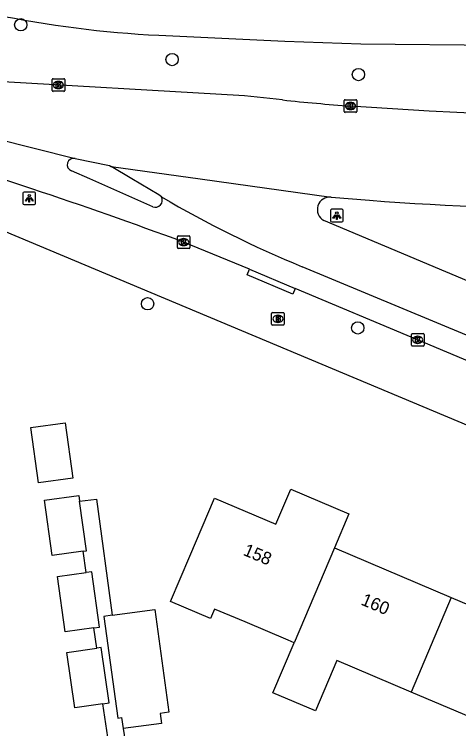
# Model space of a CAD drawing. Extents: x 162074 to 163034, y 381824 to 382557.
# Drawn here: x 162501.6 to 162536.8, y 382456.5 to 382513 of the extents above; entities that cross this region are included whole.
import ezdxf

# ---------------------------------------------------------------- set-up
doc = ezdxf.new("R2010")
doc.units = 0
for name, color, linetype in [('IMGEO_Boom', 7, 'Continuous'), ('IMGEO_Brandkraan', 7, 'Continuous'), ('IMGEO_Fietspad_gesloten', 7, 'Continuous'), ('IMGEO_Kolk', 7, 'Continuous'), ('IMGEO_Lichtpunt', 7, 'Continuous'), ('IMGEO_Pand', 7, 'Continuous'), ('IMGEO_Pand_nummerreeks', 7, 'Continuous'), ('IMGEO_Rijbaan_lokaal_gesloten', 7, 'Continuous'), ('IMGEO_Rijbaan_lokaal_open', 7, 'Continuous'), ('IMGEO_Voetpad_open', 7, 'Continuous')]:
    doc.layers.add(name, color=color, linetype=linetype)

msp = doc.modelspace()

# ---------------------------------------------------------------- linework, layer by layer
at = {"layer": 'IMGEO_Boom'}
for centre in [(162502.12, 382512.2), (162514.109, 382509.442), (162528.864, 382508.257), (162512.169, 382490.11), (162528.813, 382488.194)]:
    msp.add_circle(centre, 0.489, dxfattribs=at)
at = {"layer": 'IMGEO_Brandkraan'}
for p, q in [((162521.991, 382488.49), (162521.991, 382489.342)), ((162522.066, 382489.416), (162522.918, 382489.416)), ((162522.479, 382489.196), (162522.504, 382489.196)), ((162522.992, 382489.342), (162522.992, 382488.49)), ((162522.502, 382488.636), (162522.477, 382488.636)), ((162522.918, 382488.416), (162522.066, 382488.416))]:
    msp.add_line(p, q, dxfattribs=at)
for points in [[(162521.991, 382488.49), (162521.991, 382489.342)], [(162522.066, 382489.416), (162522.918, 382489.416)], [(162522.339, 382489.116), (162522.339, 382488.716), (162522.552, 382488.716)], [(162522.57, 382489.116), (162522.339, 382489.116)], [(162522.992, 382489.342), (162522.992, 382488.49)], [(162522.518, 382489.035), (162522.464, 382489.035), (162522.464, 382488.959)], [(162522.464, 382488.959), (162522.517, 382488.959)], [(162522.526, 382488.883), (162522.464, 382488.883), (162522.464, 382488.802)], [(162522.464, 382488.802), (162522.526, 382488.802)], [(162522.918, 382488.416), (162522.066, 382488.416)]]:
    msp.add_lwpolyline(points, dxfattribs=at)
for centre, radius, start, end in [((162522.068, 382489.34), 0.0765, 91.552, 178.448), ((162522.068, 382489.34), 0.0765, 91.552, 178.448), ((162522.574, 382488.971), 0.145, 59.4692, 91.5367), ((162522.599, 382489.018), 0.0922, 285.5137, 58.1501), ((162522.916, 382489.34), 0.0765, 1.552, 88.448), ((162522.916, 382489.34), 0.0765, 1.552, 88.448), ((162522.068, 382488.492), 0.0765, 181.552, 268.448), ((162522.068, 382488.492), 0.0765, 181.552, 268.448), ((162522.519, 382488.997), 0.0379, 267.8285, 90.9355), ((162522.527, 382488.842), 0.0404, 269.8759, 90.5077), ((162522.558, 382488.967), 0.251, 268.6676, 293.5347), ((162522.604, 382488.826), 0.105, 301.3115, 78.989), ((162522.916, 382488.492), 0.0765, 271.552, 358.448), ((162522.916, 382488.492), 0.0765, 271.552, 358.448)]:
    msp.add_arc(centre, radius, start, end, dxfattribs=at)
for centre, major_axis, ratio, start_param, end_param in [((162522.478, 382488.916), (-0.387, 0.002), 0.722429, 4.712389, 7.853982), ((162522.503, 382488.916), (-0.39, 0.002), 0.717154, 1.570796, 4.712389)]:
    msp.add_ellipse(centre, major_axis=major_axis, ratio=ratio, start_param=start_param, end_param=end_param, dxfattribs=at)
at = {"layer": 'IMGEO_Fietspad_gesloten'}
for points in [[(162503.008, 382499.204), (162500.608, 382500), (162500.103, 382500.201), (162490.126, 382503.498), (162488.606, 382503.954)], [(162512.579, 382497.793), (162507.586, 382500), (162506.149, 382500.635)], [(162520.239, 382492.857), (162515.019, 382494.99)], [(162520.239, 382492.857), (162523.867, 382491.324)], [(162553.843, 382478.68), (162549.296, 382480.629), (162533.557, 382487.255), (162523.867, 382491.324)]]:
    msp.add_lwpolyline(points, dxfattribs=at)
for centre, radius, start, end in [((162506.308, 382501.118), 0.508, 76.4484, 251.7848), ((162376.921, 382120.599), 399.049, 69.75299, 71.58067), ((162512.782, 382498.308), 0.554, 248.4844, 27.8363)]:
    msp.add_arc(centre, radius, start, end, dxfattribs=at)
at = {"layer": 'IMGEO_Kolk'}
for p, q in [((162504.598, 382507.003), (162504.598, 382507.855)), ((162504.673, 382507.929), (162505.525, 382507.929)), ((162505.599, 382507.855), (162505.599, 382507.003)), ((162505.109, 382507.149), (162505.084, 382507.149)), ((162505.086, 382507.709), (162505.111, 382507.709)), ((162505.525, 382506.929), (162504.673, 382506.929)), ((162527.74, 382505.34), (162527.74, 382506.192)), ((162527.815, 382506.266), (162528.667, 382506.266)), ((162528.228, 382506.046), (162528.253, 382506.046)), ((162528.741, 382506.192), (162528.741, 382505.34)), ((162528.251, 382505.486), (162528.226, 382505.486)), ((162528.667, 382505.266), (162527.815, 382505.266)), ((162514.522, 382494.564), (162514.522, 382495.416)), ((162514.597, 382495.49), (162515.449, 382495.49)), ((162515.01, 382495.27), (162515.035, 382495.27)), ((162515.523, 382495.416), (162515.523, 382494.564)), ((162515.033, 382494.71), (162515.008, 382494.71)), ((162515.449, 382494.49), (162514.597, 382494.49)), ((162533.06, 382486.828), (162533.06, 382487.68)), ((162533.135, 382487.754), (162533.987, 382487.754)), ((162533.548, 382487.534), (162533.573, 382487.534)), ((162534.061, 382487.68), (162534.061, 382486.828)), ((162533.571, 382486.974), (162533.546, 382486.974)), ((162533.987, 382486.754), (162533.135, 382486.754))]:
    msp.add_line(p, q, dxfattribs=at)
for points in [[(162504.598, 382507.003), (162504.598, 382507.855)], [(162504.673, 382507.929), (162505.525, 382507.929)], [(162505.599, 382507.855), (162505.599, 382507.003)], [(162504.919, 382507.629), (162505.042, 382507.629), (162505.042, 382507.478), (162505.172, 382507.629), (162505.336, 382507.629), (162505.19, 382507.478), (162505.343, 382507.229), (162505.191, 382507.229), (162505.106, 382507.393), (162505.042, 382507.326), (162505.042, 382507.229), (162504.919, 382507.229), (162504.919, 382507.629)], [(162505.525, 382506.929), (162504.673, 382506.929)], [(162527.74, 382505.34), (162527.74, 382506.192)], [(162527.815, 382506.266), (162528.667, 382506.266)], [(162528.741, 382506.192), (162528.741, 382505.34)], [(162528.061, 382505.966), (162528.184, 382505.966), (162528.184, 382505.815), (162528.314, 382505.966), (162528.478, 382505.966), (162528.332, 382505.815), (162528.485, 382505.566), (162528.333, 382505.566), (162528.248, 382505.73), (162528.184, 382505.663), (162528.184, 382505.566), (162528.061, 382505.566), (162528.061, 382505.966)], [(162528.667, 382505.266), (162527.815, 382505.266)], [(162514.522, 382494.564), (162514.522, 382495.416)], [(162514.597, 382495.49), (162515.449, 382495.49)], [(162515.523, 382495.416), (162515.523, 382494.564)], [(162514.843, 382495.19), (162514.966, 382495.19), (162514.966, 382495.039), (162515.096, 382495.19), (162515.26, 382495.19), (162515.114, 382495.039), (162515.267, 382494.79), (162515.115, 382494.79), (162515.03, 382494.954), (162514.966, 382494.887), (162514.966, 382494.79), (162514.843, 382494.79), (162514.843, 382495.19)], [(162515.449, 382494.49), (162514.597, 382494.49)], [(162533.06, 382486.828), (162533.06, 382487.68)], [(162533.135, 382487.754), (162533.987, 382487.754)], [(162533.381, 382487.454), (162533.504, 382487.454), (162533.504, 382487.303), (162533.634, 382487.454), (162533.798, 382487.454), (162533.652, 382487.303), (162533.805, 382487.054), (162533.653, 382487.054), (162533.568, 382487.218), (162533.504, 382487.151), (162533.504, 382487.054), (162533.381, 382487.054), (162533.381, 382487.454)], [(162534.061, 382487.68), (162534.061, 382486.828)], [(162533.987, 382486.754), (162533.135, 382486.754)]]:
    msp.add_lwpolyline(points, dxfattribs=at)
for centre, start, end in [((162504.675, 382507.853), 91.552, 178.448), ((162504.675, 382507.853), 91.552, 178.448), ((162505.523, 382507.853), 1.552, 88.448), ((162505.523, 382507.853), 1.552, 88.448), ((162504.675, 382507.005), 181.552, 268.448), ((162504.675, 382507.005), 181.552, 268.448), ((162505.523, 382507.005), 271.552, 358.448), ((162505.523, 382507.005), 271.552, 358.448), ((162527.817, 382506.19), 91.552, 178.448), ((162527.817, 382506.19), 91.552, 178.448), ((162528.665, 382506.19), 1.552, 88.448), ((162528.665, 382506.19), 1.552, 88.448), ((162527.817, 382505.342), 181.552, 268.448), ((162527.817, 382505.342), 181.552, 268.448), ((162528.665, 382505.342), 271.552, 358.448), ((162528.665, 382505.342), 271.552, 358.448), ((162514.599, 382495.414), 91.552, 178.448), ((162514.599, 382495.414), 91.552, 178.448), ((162515.447, 382495.414), 1.552, 88.448), ((162515.447, 382495.414), 1.552, 88.448), ((162514.599, 382494.566), 181.552, 268.448), ((162514.599, 382494.566), 181.552, 268.448), ((162515.447, 382494.566), 271.552, 358.448), ((162515.447, 382494.566), 271.552, 358.448), ((162533.137, 382487.678), 91.552, 178.448), ((162533.137, 382487.678), 91.552, 178.448), ((162533.985, 382487.678), 1.552, 88.448), ((162533.985, 382487.678), 1.552, 88.448), ((162533.137, 382486.83), 181.552, 268.448), ((162533.137, 382486.83), 181.552, 268.448), ((162533.985, 382486.83), 271.552, 358.448), ((162533.985, 382486.83), 271.552, 358.448)]:
    msp.add_arc(centre, 0.0765, start, end, dxfattribs=at)
for centre, major_axis, ratio, start_param, end_param in [((162505.085, 382507.429), (-0.387, 0.002), 0.722429, 4.712389, 7.853982), ((162505.11, 382507.429), (-0.39, 0.002), 0.717154, 1.570796, 4.712389), ((162528.227, 382505.766), (-0.387, 0.002), 0.722429, 4.712389, 7.853982), ((162528.252, 382505.766), (-0.39, 0.002), 0.717154, 1.570796, 4.712389), ((162515.009, 382494.99), (-0.387, 0.002), 0.722429, 4.712389, 7.853982), ((162515.034, 382494.99), (-0.39, 0.002), 0.717154, 1.570796, 4.712389), ((162533.547, 382487.254), (-0.387, 0.002), 0.722429, 4.712389, 7.853982), ((162533.572, 382487.254), (-0.39, 0.002), 0.717154, 1.570796, 4.712389)]:
    msp.add_ellipse(centre, major_axis=major_axis, ratio=ratio, start_param=start_param, end_param=end_param, dxfattribs=at)
at = {"layer": 'IMGEO_Lichtpunt'}
for p, q in [((162502.295, 382498.862), (162502.295, 382498.055)), ((162502.295, 382498.862), (162502.295, 382498.055)), ((162503.197, 382498.957), (162502.389, 382498.957)), ((162503.197, 382498.957), (162502.389, 382498.957)), ((162503.291, 382498.055), (162503.291, 382498.862)), ((162503.291, 382498.055), (162503.291, 382498.862)), ((162502.389, 382497.961), (162503.197, 382497.961)), ((162502.389, 382497.961), (162503.197, 382497.961)), ((162527.562, 382497.586), (162526.754, 382497.586)), ((162527.562, 382497.586), (162526.754, 382497.586)), ((162526.66, 382497.491), (162526.66, 382496.684)), ((162526.66, 382497.491), (162526.66, 382496.684)), ((162527.656, 382496.684), (162527.656, 382497.491)), ((162527.656, 382496.684), (162527.656, 382497.491)), ((162526.754, 382496.59), (162527.562, 382496.59)), ((162526.754, 382496.59), (162527.562, 382496.59))]:
    msp.add_line(p, q, dxfattribs=at)
for points in [[(162502.669, 382498.526), (162502.708, 382498.498), (162502.52, 382498.236), (162502.482, 382498.263), (162502.669, 382498.526)], [(162502.771, 382498.478), (162502.818, 382498.478), (162502.818, 382498.156), (162502.771, 382498.156), (162502.771, 382498.478)], [(162502.881, 382498.498), (162502.919, 382498.525), (162503.106, 382498.263), (162503.067, 382498.235), (162502.881, 382498.498)], [(162527.034, 382497.155), (162527.073, 382497.127), (162526.885, 382496.865), (162526.847, 382496.892), (162527.034, 382497.155)], [(162527.136, 382497.107), (162527.183, 382497.107), (162527.183, 382496.785), (162527.136, 382496.785), (162527.136, 382497.107)], [(162527.246, 382497.127), (162527.284, 382497.154), (162527.471, 382496.892), (162527.432, 382496.864), (162527.246, 382497.127)]]:
    msp.add_lwpolyline(points, dxfattribs=at)
for centre in [(162502.794, 382498.66), (162527.159, 382497.289)]:
    msp.add_circle(centre, 0.0994, dxfattribs=at)
for centre, start, end in [((162502.389, 382498.862), 90, 180), ((162502.389, 382498.862), 90, 180), ((162503.197, 382498.862), 0, 90), ((162503.197, 382498.862), 0, 90), ((162502.389, 382498.055), 180, 270), ((162502.389, 382498.055), 180, 270), ((162503.197, 382498.055), 270, 0), ((162503.197, 382498.055), 270, 360), ((162526.754, 382497.491), 90, 180), ((162526.754, 382497.491), 90, 180), ((162527.562, 382497.491), 0, 90), ((162527.562, 382497.491), 0, 90), ((162526.754, 382496.684), 180, 270), ((162526.754, 382496.684), 180, 270), ((162527.562, 382496.684), 270, 0), ((162527.562, 382496.684), 270, 360)]:
    msp.add_arc(centre, 0.0946, start, end, dxfattribs=at)
at = {"layer": 'IMGEO_Pand'}
for points in [[(162503.53, 382475.927), (162502.911, 382480.306), (162505.629, 382480.69), (162506.248, 382476.311), (162503.53, 382475.927)], [(162507.053, 382470.512), (162504.611, 382470.166), (162503.992, 382474.546), (162506.709, 382474.93), (162506.772, 382474.487)], [(162523.766, 382463.272), (162523.294, 382463.472), (162519.902, 382464.91), (162517.475, 382465.939), (162517.154, 382465.181), (162513.979, 382466.527), (162515.504, 382470.123), (162517.456, 382474.726), (162522.33, 382472.659), (162523.506, 382475.432), (162528.109, 382473.481), (162526.962, 382470.776)], [(162507.053, 382470.512), (162507.328, 382470.551), (162506.772, 382474.487)], [(162526.962, 382470.776), (162523.766, 382463.272)], [(162526.962, 382470.776), (162536.214, 382466.853)], [(162507.913, 382464.443), (162505.649, 382464.123), (162505.03, 382468.502), (162507.292, 382468.822)], [(162507.913, 382464.443), (162508.367, 382464.507), (162507.748, 382468.887), (162507.292, 382468.822)], [(162536.214, 382466.853), (162545.458, 382462.933), (162544.778, 382461.328), (162545.416, 382461.057), (162544.064, 382457.868), (162543.471, 382458.119), (162539.438, 382448.608), (162536.492, 382449.857), (162539.383, 382456.674), (162538.978, 382456.846), (162533.041, 382459.363)], [(162536.214, 382466.853), (162533.041, 382459.363)], [(162509.368, 382465.445), (162512.727, 382465.906), (162513.844, 382457.77), (162513.167, 382457.677), (162513.276, 382456.884), (162510.228, 382456.466)], [(162509.368, 382465.445), (162508.697, 382465.353), (162509.802, 382457.303), (162510.108, 382457.345), (162510.228, 382456.466)], [(162533.041, 382459.363), (162527.152, 382461.86), (162525.471, 382457.865), (162522.077, 382459.304), (162523.766, 382463.272)], [(162508.618, 382458.428), (162506.394, 382458.114), (162505.774, 382462.493), (162508.142, 382462.828)], [(162508.618, 382458.428), (162509.111, 382458.498), (162508.492, 382462.878), (162508.142, 382462.828)]]:
    msp.add_lwpolyline(points, dxfattribs=at)
at = {"layer": 'IMGEO_Rijbaan_lokaal_gesloten'}
for points in [[(162513.055, 382511.37), (162523.035, 382510.893), (162529.055, 382510.701), (162539.954, 382510.571)], [(162522.847, 382506.244), (162519.844, 382506.585), (162498.887, 382507.785)], [(162489.028, 382505.962), (162498.724, 382503.538), (162500, 382503.219), (162506.427, 382501.612)], [(162549.777, 382504.959), (162543.671, 382504.983), (162538.859, 382505.153), (162534.465, 382505.356), (162528.241, 382505.765)], [(162506.427, 382501.612), (162509.137, 382501.043), (162509.284, 382500.985)], [(162509.284, 382500.985), (162516.337, 382500), (162526.719, 382498.55)], [(162526.719, 382498.55), (162529.739, 382498.302)]]:
    msp.add_lwpolyline(points, dxfattribs=at)
for centre, radius, start, end in [((162517.107, 382595.453), 84.18, 258.27467, 267.24093), ((162540.559, 382675.089), 169.772, 264.01149, 265.83913), ((162547.316, 382725.761), 228.137, 265.58112, 275.23655)]:
    msp.add_arc(centre, radius, start, end, dxfattribs=at)
at = {"layer": 'IMGEO_Rijbaan_lokaal_open'}
for points in [[(162513.272, 382498.567), (162513.054, 382498.722), (162510.925, 382500), (162509.284, 382500.985)], [(162540.63, 382490.602), (162526.122, 382496.703)], [(162566.754, 382475.425), (162524.41, 382493.044)]]:
    msp.add_lwpolyline(points, dxfattribs=at)
for centre, radius, start, end in [((162557.485, 382573.737), 87.209, 239.53716, 247.71197), ((162526.6, 382497.569), 0.989, 83.0633, 241.1123)]:
    msp.add_arc(centre, radius, start, end, dxfattribs=at)
at = {"layer": 'IMGEO_Voetpad_open'}
for points in [[(162564.361, 382469.237), (162500, 382496.185), (162492.214, 382499.445)], [(162523.867, 382491.324), (162523.673, 382490.864), (162520.045, 382492.397), (162520.239, 382492.857)], [(162506.772, 382474.487), (162508.107, 382474.631), (162509.368, 382465.445)], [(162507.292, 382468.822), (162507.053, 382470.512)], [(162508.142, 382462.828), (162507.913, 382464.443)], [(162484.672, 382451.644), (162509.008, 382455.786), (162508.618, 382458.428)], [(162510.228, 382456.466), (162512.494, 382442.149)]]:
    msp.add_lwpolyline(points, dxfattribs=at)

# ---------------------------------------------------------------- texts
at = {"layer": 'IMGEO_Pand_nummerreeks'}
for s, p in [('158', (162519.667, 382470.236)), ('160', (162529.001, 382466.305))]:
    msp.add_text(s, height=1, rotation=337.1619, dxfattribs=at).set_placement(p)

doc.saveas('drawing.dxf')
